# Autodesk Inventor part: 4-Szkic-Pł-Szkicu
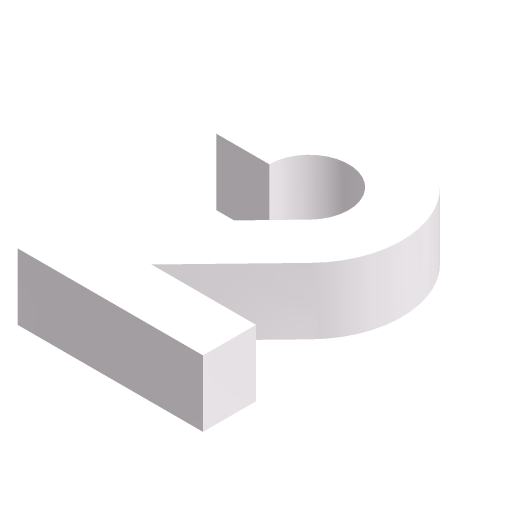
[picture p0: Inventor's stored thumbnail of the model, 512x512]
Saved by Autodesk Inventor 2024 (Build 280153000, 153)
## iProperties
Company: ATC
Shininess: 0.0
Length Units: 11269
Angle Units: 11279
Time Units: 11290
Mass Units: 11283
Length Display Precision: 1
Angle Display Precision: 2
Compacted: True
Created: 2023-03
Part Number: 4-Szkic-Pł-Szkicu
Document SubType Name: Modeling
Designer: Andrzej Jaskulski
Material: Kurs-AJ
Density: 1 g/cm^3
Appearance: Kurs-AJ
Checked By: A.J.
Engr Approved By: Andrzej Jaskulski
Mfg Approved By: Andrzej Jaskulski
Authority: A.J.
Density: 0.0
Volumn: 0.0
Area: 0.0
PropertySet Name: Model Information
Control State: 0
Master: False
Checked Out: False
Title: A.J.: Kurs R2024-MEP
Author: Andrzej Jaskulski
Revision Number: 1/24
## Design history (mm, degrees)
sketch "Dwójka"
  geometry: L1 (-140, 0.063)-(0, 0.063) reference; L2 (0, 0.063)-(0, -34.263) reference; L3 (0, -149.937)-(-40, -149.937); L4 (-140, 0.063)-(-140, -39.937); L5 (-140, -39.937)-(-61.086, -39.937); L6 (-61.086, -39.937)-(-120.354, -101.311); L7 (-91.58, -129.097)-(0, -34.263); A1 r 30 centre (-70, -149.937) between (-91.58, -129.097) and (-40, -149.937); A2 r 70 centre (-70, -149.937) between (-120.354, -101.311) and (0, -149.937)
  constraints: 14 end point, 4 perpendicular, 4 point on circle, 2 centre point, 2 horizontal, 2 parallel, 2 tangent, 1 coincident, 1 vertical, 1 other
  dimensions: "d2" = 140 distance of L1.start L1.end; "d5" = 150 vertical distance of A1.centre L1.end; "d6" = 70 horizontal distance of L1.end A1.centre; "d8" = 46 deg angle of L6 L5; "d9" = 150 distance of L3.start L1.end (= d5); "d11" = 30 radius of A1; "d12" = 70 radius of A2
extrude "Extrusion1" new body sketch "Dwójka" distance "d13" = 50; taper "d14" = 0 deg
node "Płaszczyzna nad dwójką"
node "Płaszczyzna odsunięta od główki"
node "Bryła1"
node "Korpusy bryłowe"
node "Korpusy powierzchniowe"
